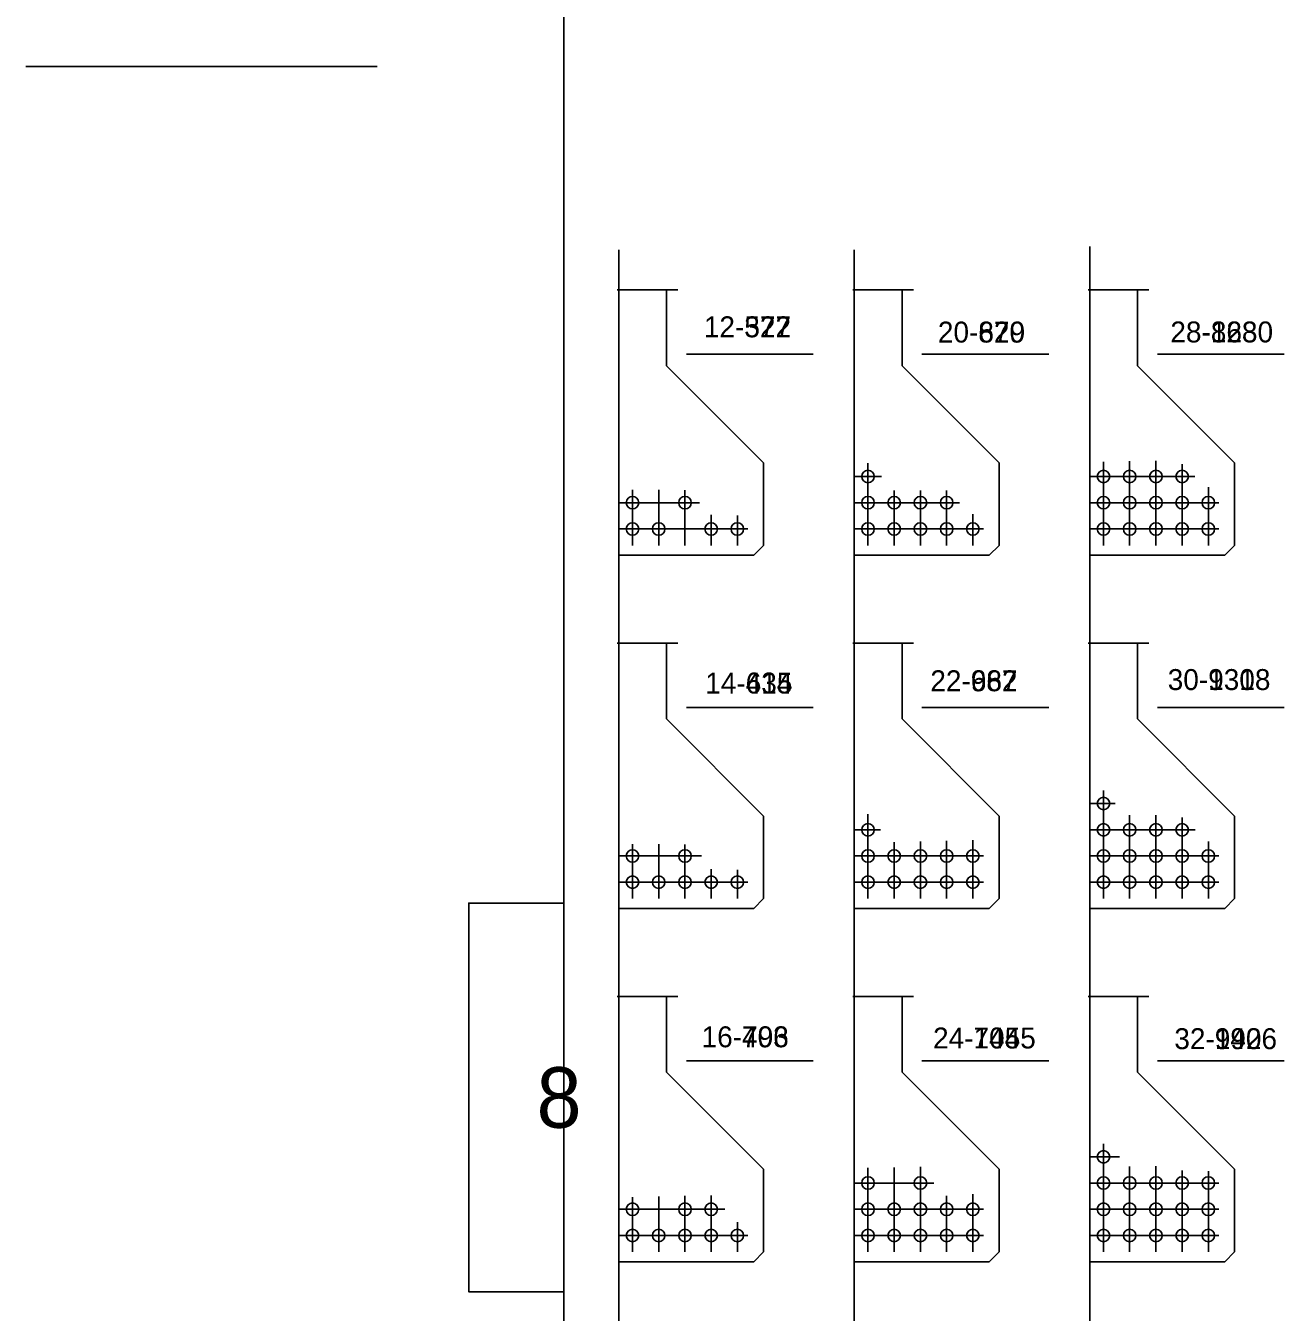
# Model space of a CAD drawing. Extents: x 1005.3 to 1101.9, y 1996.5 to 2073.3.
# Drawn here: x 1005.28 to 1025.32, y 2020.32 to 2040.81 of the extents above; entities that cross this region are included whole.
import ezdxf

# ---------------------------------------------------------------- set-up
doc = ezdxf.new("R2010")
doc.units = 0
for name, color, linetype in [('Level 1', 7, 'Continuous'), ('Level 37', 7, 'Continuous'), ('Level 8', 7, 'Continuous'), ('Level 9', 7, 'Continuous')]:
    doc.layers.add(name, color=color, linetype=linetype)

msp = doc.modelspace()

# ---------------------------------------------------------------- linework, layer by layer
at = {"layer": 'Level 1'}
msp.add_line((1013.852, 2012.158), (1013.852, 2068.156), dxfattribs=at)
msp.add_lwpolyline([(1013.851, 2026.837), (1012.338, 2026.837), (1012.338, 2020.647), (1013.851, 2020.647)], close=True, dxfattribs=at)
at = {"layer": 'Level 37'}
msp.add_line((1010.879, 2040.157), (1005.282, 2040.157), dxfattribs=at)
at = {"layer": 'Level 8'}
for p, q in [((1022.226, 2014.966), (1022.226, 2037.289)), ((1014.726, 2015.012), (1014.726, 2037.24)), ((1018.476, 2015.012), (1018.476, 2037.24)), ((1014.703, 2036.601), (1015.668, 2036.601)), ((1015.488, 2035.393), (1015.488, 2036.594)), ((1018.453, 2036.601), (1019.418, 2036.601)), ((1019.238, 2035.393), (1019.238, 2036.594)), ((1022.203, 2036.601), (1023.168, 2036.601)), ((1022.988, 2035.393), (1022.988, 2036.594)), ((1015.804, 2035.577), (1017.824, 2035.577)), ((1019.554, 2035.577), (1021.574, 2035.577)), ((1023.304, 2035.577), (1025.324, 2035.577)), ((1017.032, 2033.848), (1015.488, 2035.393)), ((1020.782, 2033.848), (1019.238, 2035.393)), ((1024.532, 2033.848), (1022.988, 2035.393)), ((1017.032, 2032.533), (1017.032, 2033.848)), ((1018.695, 2032.533), (1018.695, 2033.842)), ((1020.782, 2032.533), (1020.782, 2033.848)), ((1022.445, 2032.533), (1022.445, 2033.865)), ((1022.862, 2032.533), (1022.862, 2033.871)), ((1023.28, 2032.533), (1023.28, 2033.878)), ((1023.697, 2032.533), (1023.697, 2033.827)), ((1024.532, 2032.533), (1024.532, 2033.848)), ((1018.476, 2033.629), (1018.911, 2033.629)), ((1022.226, 2033.629), (1023.902, 2033.629)), ((1014.945, 2032.533), (1014.945, 2033.417)), ((1015.362, 2032.533), (1015.362, 2033.415)), ((1015.78, 2032.533), (1015.78, 2033.413)), ((1019.112, 2032.533), (1019.112, 2033.405)), ((1019.53, 2032.533), (1019.53, 2033.405)), ((1019.947, 2032.533), (1019.947, 2033.405)), ((1024.115, 2032.533), (1024.115, 2033.459)), ((1014.726, 2033.212), (1016.01, 2033.212)), ((1018.476, 2033.212), (1020.152, 2033.212)), ((1018.476, 2033.212), (1020.144, 2033.212)), ((1022.226, 2033.212), (1024.283, 2033.212)), ((1016.197, 2032.533), (1016.197, 2033.017)), ((1016.615, 2032.533), (1016.615, 2033.009)), ((1020.365, 2032.533), (1020.365, 2033.028)), ((1014.726, 2032.794), (1016.783, 2032.794)), ((1018.476, 2032.794), (1020.533, 2032.794)), ((1022.226, 2032.794), (1024.283, 2032.794)), ((1016.876, 2032.376), (1017.032, 2032.533)), ((1020.626, 2032.376), (1020.782, 2032.533)), ((1024.376, 2032.376), (1024.532, 2032.533)), ((1016.876, 2032.376), (1014.726, 2032.376)), ((1020.626, 2032.376), (1018.476, 2032.376)), ((1024.376, 2032.376), (1022.226, 2032.376)), ((1014.703, 2030.976), (1015.668, 2030.976)), ((1015.488, 2029.768), (1015.488, 2030.969)), ((1018.453, 2030.976), (1019.418, 2030.976)), ((1019.238, 2029.768), (1019.238, 2030.969)), ((1022.203, 2030.976), (1023.168, 2030.976)), ((1022.988, 2029.768), (1022.988, 2030.969)), ((1015.804, 2029.952), (1017.824, 2029.952)), ((1019.554, 2029.952), (1021.574, 2029.952)), ((1023.304, 2029.952), (1025.324, 2029.952)), ((1017.032, 2028.223), (1015.488, 2029.768)), ((1020.782, 2028.223), (1019.238, 2029.768)), ((1024.532, 2028.223), (1022.988, 2029.768)), ((1022.445, 2026.908), (1022.445, 2028.632)), ((1018.695, 2026.908), (1018.695, 2028.255)), ((1022.226, 2028.422), (1022.633, 2028.422)), ((1022.862, 2026.908), (1022.862, 2028.235)), ((1023.28, 2026.908), (1023.28, 2028.239)), ((1017.032, 2026.908), (1017.032, 2028.223)), ((1020.782, 2026.908), (1020.782, 2028.223)), ((1023.697, 2026.908), (1023.697, 2028.202)), ((1024.532, 2026.908), (1024.532, 2028.223)), ((1018.476, 2028.004), (1018.894, 2028.004)), ((1019.53, 2026.908), (1019.53, 2027.818)), ((1019.947, 2026.908), (1019.947, 2027.828)), ((1020.365, 2026.908), (1020.365, 2027.838)), ((1022.226, 2028.004), (1023.903, 2028.004)), ((1024.115, 2026.908), (1024.115, 2027.818)), ((1014.945, 2026.908), (1014.945, 2027.776)), ((1015.362, 2026.908), (1015.362, 2027.774)), ((1015.78, 2026.908), (1015.78, 2027.771)), ((1019.112, 2026.908), (1019.112, 2027.807)), ((1014.726, 2027.587), (1016.041, 2027.587)), ((1018.476, 2027.587), (1020.533, 2027.587)), ((1022.226, 2027.587), (1024.283, 2027.587)), ((1022.226, 2027.587), (1024.283, 2027.587)), ((1016.197, 2026.908), (1016.197, 2027.376)), ((1016.615, 2026.908), (1016.615, 2027.368)), ((1014.726, 2027.169), (1016.783, 2027.169)), ((1018.476, 2027.169), (1020.533, 2027.169)), ((1022.226, 2027.169), (1024.283, 2027.169)), ((1016.876, 2026.751), (1017.032, 2026.908)), ((1020.626, 2026.751), (1020.782, 2026.908)), ((1024.376, 2026.751), (1024.532, 2026.908)), ((1016.876, 2026.751), (1014.726, 2026.751)), ((1020.626, 2026.751), (1018.476, 2026.751)), ((1024.376, 2026.751), (1022.226, 2026.751)), ((1014.703, 2025.351), (1015.668, 2025.351)), ((1015.488, 2024.143), (1015.488, 2025.344)), ((1018.453, 2025.351), (1019.418, 2025.351)), ((1019.238, 2024.143), (1019.238, 2025.344)), ((1022.203, 2025.351), (1023.168, 2025.351)), ((1022.988, 2024.143), (1022.988, 2025.344)), ((1017.032, 2022.598), (1015.488, 2024.143)), ((1015.804, 2024.327), (1017.824, 2024.327)), ((1020.782, 2022.598), (1019.238, 2024.143)), ((1019.554, 2024.327), (1021.574, 2024.327)), ((1024.532, 2022.598), (1022.988, 2024.143)), ((1023.304, 2024.327), (1025.324, 2024.327)), ((1022.445, 2021.283), (1022.445, 2023.002)), ((1022.226, 2022.797), (1022.698, 2022.797)), ((1017.032, 2021.283), (1017.032, 2022.598)), ((1018.695, 2021.283), (1018.695, 2022.619)), ((1019.112, 2021.283), (1019.112, 2022.628)), ((1019.53, 2021.283), (1019.53, 2022.637)), ((1020.782, 2021.283), (1020.782, 2022.598)), ((1022.862, 2021.283), (1022.862, 2022.643)), ((1023.28, 2021.283), (1023.28, 2022.647)), ((1023.697, 2021.283), (1023.697, 2022.577)), ((1024.115, 2021.283), (1024.115, 2022.569)), ((1024.532, 2021.283), (1024.532, 2022.598)), ((1018.476, 2022.379), (1019.742, 2022.379)), ((1022.226, 2022.379), (1024.283, 2022.379)), ((1014.945, 2021.283), (1014.945, 2022.155)), ((1015.362, 2021.283), (1015.362, 2022.165)), ((1015.78, 2021.283), (1015.78, 2022.174)), ((1016.197, 2021.283), (1016.197, 2022.183)), ((1019.947, 2021.283), (1019.947, 2022.173)), ((1020.365, 2021.283), (1020.365, 2022.2)), ((1014.726, 2021.962), (1016.416, 2021.962)), ((1018.476, 2021.962), (1020.533, 2021.962)), ((1022.226, 2021.962), (1024.283, 2021.962)), ((1016.615, 2021.283), (1016.615, 2021.755)), ((1014.726, 2021.544), (1016.783, 2021.544)), ((1018.476, 2021.544), (1020.533, 2021.544)), ((1022.226, 2021.544), (1024.283, 2021.544)), ((1016.876, 2021.126), (1017.032, 2021.283)), ((1020.626, 2021.126), (1020.782, 2021.283)), ((1024.376, 2021.126), (1024.532, 2021.283)), ((1016.876, 2021.126), (1014.726, 2021.126)), ((1020.626, 2021.126), (1018.476, 2021.126)), ((1024.376, 2021.126), (1022.226, 2021.126))]:
    msp.add_line(p, q, dxfattribs=at)
for centre in [(1018.695, 2033.629), (1022.445, 2033.629), (1022.862, 2033.629), (1023.28, 2033.629), (1023.697, 2033.629), (1014.945, 2033.212), (1015.78, 2033.212), (1018.695, 2033.212), (1019.112, 2033.212), (1019.53, 2033.212), (1019.947, 2033.212), (1022.445, 2033.212), (1022.862, 2033.212), (1023.28, 2033.212), (1023.697, 2033.212), (1024.115, 2033.212), (1014.945, 2032.794), (1015.362, 2032.794), (1016.197, 2032.794), (1016.615, 2032.794), (1018.695, 2032.794), (1019.112, 2032.794), (1019.53, 2032.794), (1019.947, 2032.794), (1020.365, 2032.794), (1022.445, 2032.794), (1022.862, 2032.794), (1023.28, 2032.794), (1023.697, 2032.794), (1024.115, 2032.794), (1022.445, 2028.422), (1018.695, 2028.004), (1022.445, 2028.004), (1022.862, 2028.004), (1023.28, 2028.004), (1023.697, 2028.004), (1014.945, 2027.587), (1015.78, 2027.587), (1018.695, 2027.587), (1019.112, 2027.587), (1019.53, 2027.587), (1019.947, 2027.587), (1020.365, 2027.587), (1022.445, 2027.587), (1022.862, 2027.587), (1023.28, 2027.587), (1023.697, 2027.587), (1024.115, 2027.587), (1014.945, 2027.169), (1015.362, 2027.169), (1015.78, 2027.169), (1016.197, 2027.169), (1016.615, 2027.169), (1018.695, 2027.169), (1019.112, 2027.169), (1019.53, 2027.169), (1019.947, 2027.169), (1020.365, 2027.169), (1022.445, 2027.169), (1022.862, 2027.169), (1023.28, 2027.169), (1023.697, 2027.169), (1024.115, 2027.169), (1022.445, 2022.797), (1018.695, 2022.379), (1019.53, 2022.379), (1022.445, 2022.379), (1022.862, 2022.379), (1023.28, 2022.379), (1023.697, 2022.379), (1024.115, 2022.379), (1014.945, 2021.962), (1015.78, 2021.962), (1016.197, 2021.962), (1018.695, 2021.962), (1019.112, 2021.962), (1019.53, 2021.962), (1019.947, 2021.962), (1020.365, 2021.962), (1022.445, 2021.962), (1022.862, 2021.962), (1023.28, 2021.962), (1023.697, 2021.962), (1024.115, 2021.962), (1014.945, 2021.544), (1015.362, 2021.544), (1015.78, 2021.544), (1016.197, 2021.544), (1016.615, 2021.544), (1018.695, 2021.544), (1019.112, 2021.544), (1019.53, 2021.544), (1019.947, 2021.544), (1020.365, 2021.544), (1022.445, 2021.544), (1022.862, 2021.544), (1023.28, 2021.544), (1023.697, 2021.544), (1024.115, 2021.544)]:
    msp.add_circle(centre, 0.0996, dxfattribs=at)
at = {"layer": 'Level 9'}
for p, q in [((1022.226, 2014.966), (1022.226, 2037.289)), ((1014.726, 2015.012), (1014.726, 2037.24)), ((1018.476, 2015.012), (1018.476, 2037.24)), ((1014.703, 2036.601), (1015.668, 2036.601)), ((1015.488, 2035.393), (1015.488, 2036.594)), ((1018.453, 2036.601), (1019.418, 2036.601)), ((1019.238, 2035.393), (1019.238, 2036.594)), ((1022.203, 2036.601), (1023.168, 2036.601)), ((1022.988, 2035.393), (1022.988, 2036.594)), ((1015.804, 2035.577), (1017.824, 2035.577)), ((1019.554, 2035.577), (1021.574, 2035.577)), ((1023.304, 2035.577), (1025.324, 2035.577)), ((1017.032, 2033.848), (1015.488, 2035.393)), ((1020.782, 2033.848), (1019.238, 2035.393)), ((1024.532, 2033.848), (1022.988, 2035.393)), ((1017.032, 2032.533), (1017.032, 2033.848)), ((1018.695, 2032.533), (1018.695, 2033.842)), ((1020.782, 2032.533), (1020.782, 2033.848)), ((1022.445, 2032.533), (1022.445, 2033.865)), ((1022.862, 2032.533), (1022.862, 2033.871)), ((1023.28, 2032.533), (1023.28, 2033.878)), ((1023.697, 2032.533), (1023.697, 2033.827)), ((1024.532, 2032.533), (1024.532, 2033.848)), ((1018.476, 2033.629), (1018.911, 2033.629)), ((1022.226, 2033.629), (1023.902, 2033.629)), ((1014.945, 2032.533), (1014.945, 2033.417)), ((1015.362, 2032.533), (1015.362, 2033.415)), ((1015.78, 2032.533), (1015.78, 2033.413)), ((1019.112, 2032.533), (1019.112, 2033.405)), ((1019.53, 2032.533), (1019.53, 2033.405)), ((1019.947, 2032.533), (1019.947, 2033.405)), ((1024.115, 2032.533), (1024.115, 2033.459)), ((1014.726, 2033.212), (1016.01, 2033.212)), ((1018.476, 2033.212), (1020.152, 2033.212)), ((1018.476, 2033.212), (1020.144, 2033.212)), ((1022.226, 2033.212), (1024.283, 2033.212)), ((1016.197, 2032.533), (1016.197, 2033.017)), ((1016.615, 2032.533), (1016.615, 2033.009)), ((1020.365, 2032.533), (1020.365, 2033.028)), ((1014.726, 2032.794), (1016.783, 2032.794)), ((1018.476, 2032.794), (1020.533, 2032.794)), ((1022.226, 2032.794), (1024.283, 2032.794)), ((1016.876, 2032.376), (1017.032, 2032.533)), ((1020.626, 2032.376), (1020.782, 2032.533)), ((1024.376, 2032.376), (1024.532, 2032.533)), ((1016.876, 2032.376), (1014.726, 2032.376)), ((1020.626, 2032.376), (1018.476, 2032.376)), ((1024.376, 2032.376), (1022.226, 2032.376)), ((1014.703, 2030.976), (1015.668, 2030.976)), ((1015.488, 2029.768), (1015.488, 2030.969)), ((1018.453, 2030.976), (1019.418, 2030.976)), ((1019.238, 2029.768), (1019.238, 2030.969)), ((1022.203, 2030.976), (1023.168, 2030.976)), ((1022.988, 2029.768), (1022.988, 2030.969)), ((1015.804, 2029.952), (1017.824, 2029.952)), ((1019.554, 2029.952), (1021.574, 2029.952)), ((1023.304, 2029.952), (1025.324, 2029.952)), ((1017.032, 2028.223), (1015.488, 2029.768)), ((1020.782, 2028.223), (1019.238, 2029.768)), ((1024.532, 2028.223), (1022.988, 2029.768)), ((1022.445, 2026.908), (1022.445, 2028.632)), ((1018.695, 2026.908), (1018.695, 2028.255)), ((1022.226, 2028.422), (1022.633, 2028.422)), ((1022.862, 2026.908), (1022.862, 2028.235)), ((1023.28, 2026.908), (1023.28, 2028.239)), ((1017.032, 2026.908), (1017.032, 2028.223)), ((1020.782, 2026.908), (1020.782, 2028.223)), ((1023.697, 2026.908), (1023.697, 2028.202)), ((1024.532, 2026.908), (1024.532, 2028.223)), ((1018.476, 2028.004), (1018.894, 2028.004)), ((1019.53, 2026.908), (1019.53, 2027.818)), ((1019.947, 2026.908), (1019.947, 2027.828)), ((1020.365, 2026.908), (1020.365, 2027.838)), ((1022.226, 2028.004), (1023.903, 2028.004)), ((1024.115, 2026.908), (1024.115, 2027.818)), ((1014.945, 2026.908), (1014.945, 2027.776)), ((1015.362, 2026.908), (1015.362, 2027.774)), ((1015.78, 2026.908), (1015.78, 2027.771)), ((1019.112, 2026.908), (1019.112, 2027.807)), ((1014.726, 2027.587), (1016.041, 2027.587)), ((1018.476, 2027.587), (1020.533, 2027.587)), ((1022.226, 2027.587), (1024.283, 2027.587)), ((1022.226, 2027.587), (1024.283, 2027.587)), ((1016.197, 2026.908), (1016.197, 2027.376)), ((1016.615, 2026.908), (1016.615, 2027.368)), ((1014.726, 2027.169), (1016.783, 2027.169)), ((1018.476, 2027.169), (1020.533, 2027.169)), ((1022.226, 2027.169), (1024.283, 2027.169)), ((1016.876, 2026.751), (1017.032, 2026.908)), ((1020.626, 2026.751), (1020.782, 2026.908)), ((1024.376, 2026.751), (1024.532, 2026.908)), ((1016.876, 2026.751), (1014.726, 2026.751)), ((1020.626, 2026.751), (1018.476, 2026.751)), ((1024.376, 2026.751), (1022.226, 2026.751)), ((1014.703, 2025.351), (1015.668, 2025.351)), ((1015.488, 2024.143), (1015.488, 2025.344)), ((1018.453, 2025.351), (1019.418, 2025.351)), ((1019.238, 2024.143), (1019.238, 2025.344)), ((1022.203, 2025.351), (1023.168, 2025.351)), ((1022.988, 2024.143), (1022.988, 2025.344)), ((1017.032, 2022.598), (1015.488, 2024.143)), ((1015.804, 2024.327), (1017.824, 2024.327)), ((1020.782, 2022.598), (1019.238, 2024.143)), ((1019.554, 2024.327), (1021.574, 2024.327)), ((1024.532, 2022.598), (1022.988, 2024.143)), ((1023.304, 2024.327), (1025.324, 2024.327)), ((1022.445, 2021.283), (1022.445, 2023.002)), ((1022.226, 2022.797), (1022.698, 2022.797)), ((1017.032, 2021.283), (1017.032, 2022.598)), ((1018.695, 2021.283), (1018.695, 2022.619)), ((1019.112, 2021.283), (1019.112, 2022.628)), ((1019.53, 2021.283), (1019.53, 2022.637)), ((1020.782, 2021.283), (1020.782, 2022.598)), ((1022.862, 2021.283), (1022.862, 2022.643)), ((1023.28, 2021.283), (1023.28, 2022.647)), ((1023.697, 2021.283), (1023.697, 2022.577)), ((1024.115, 2021.283), (1024.115, 2022.569)), ((1024.532, 2021.283), (1024.532, 2022.598)), ((1018.476, 2022.379), (1019.742, 2022.379)), ((1022.226, 2022.379), (1024.283, 2022.379)), ((1014.945, 2021.283), (1014.945, 2022.155)), ((1015.362, 2021.283), (1015.362, 2022.165)), ((1015.78, 2021.283), (1015.78, 2022.174)), ((1016.197, 2021.283), (1016.197, 2022.183)), ((1019.947, 2021.283), (1019.947, 2022.173)), ((1020.365, 2021.283), (1020.365, 2022.2)), ((1014.726, 2021.962), (1016.416, 2021.962)), ((1018.476, 2021.962), (1020.533, 2021.962)), ((1022.226, 2021.962), (1024.283, 2021.962)), ((1016.615, 2021.283), (1016.615, 2021.755)), ((1014.726, 2021.544), (1016.783, 2021.544)), ((1018.476, 2021.544), (1020.533, 2021.544)), ((1022.226, 2021.544), (1024.283, 2021.544)), ((1016.876, 2021.126), (1017.032, 2021.283)), ((1020.626, 2021.126), (1020.782, 2021.283)), ((1024.376, 2021.126), (1024.532, 2021.283)), ((1016.876, 2021.126), (1014.726, 2021.126)), ((1020.626, 2021.126), (1018.476, 2021.126)), ((1024.376, 2021.126), (1022.226, 2021.126))]:
    msp.add_line(p, q, dxfattribs=at)
for centre in [(1018.695, 2033.629), (1022.445, 2033.629), (1022.862, 2033.629), (1023.28, 2033.629), (1023.697, 2033.629), (1014.945, 2033.212), (1015.78, 2033.212), (1018.695, 2033.212), (1019.112, 2033.212), (1019.53, 2033.212), (1019.947, 2033.212), (1022.445, 2033.212), (1022.862, 2033.212), (1023.28, 2033.212), (1023.697, 2033.212), (1024.115, 2033.212), (1014.945, 2032.794), (1015.362, 2032.794), (1016.197, 2032.794), (1016.615, 2032.794), (1018.695, 2032.794), (1019.112, 2032.794), (1019.53, 2032.794), (1019.947, 2032.794), (1020.365, 2032.794), (1022.445, 2032.794), (1022.862, 2032.794), (1023.28, 2032.794), (1023.697, 2032.794), (1024.115, 2032.794), (1022.445, 2028.422), (1018.695, 2028.004), (1022.445, 2028.004), (1022.862, 2028.004), (1023.28, 2028.004), (1023.697, 2028.004), (1014.945, 2027.587), (1015.78, 2027.587), (1018.695, 2027.587), (1019.112, 2027.587), (1019.53, 2027.587), (1019.947, 2027.587), (1020.365, 2027.587), (1022.445, 2027.587), (1022.862, 2027.587), (1023.28, 2027.587), (1023.697, 2027.587), (1024.115, 2027.587), (1014.945, 2027.169), (1015.362, 2027.169), (1015.78, 2027.169), (1016.197, 2027.169), (1016.615, 2027.169), (1018.695, 2027.169), (1019.112, 2027.169), (1019.53, 2027.169), (1019.947, 2027.169), (1020.365, 2027.169), (1022.445, 2027.169), (1022.862, 2027.169), (1023.28, 2027.169), (1023.697, 2027.169), (1024.115, 2027.169), (1022.445, 2022.797), (1018.695, 2022.379), (1019.53, 2022.379), (1022.445, 2022.379), (1022.862, 2022.379), (1023.28, 2022.379), (1023.697, 2022.379), (1024.115, 2022.379), (1014.945, 2021.962), (1015.78, 2021.962), (1016.197, 2021.962), (1018.695, 2021.962), (1019.112, 2021.962), (1019.53, 2021.962), (1019.947, 2021.962), (1020.365, 2021.962), (1022.445, 2021.962), (1022.862, 2021.962), (1023.28, 2021.962), (1023.697, 2021.962), (1024.115, 2021.962), (1014.945, 2021.544), (1015.362, 2021.544), (1015.78, 2021.544), (1016.197, 2021.544), (1016.615, 2021.544), (1018.695, 2021.544), (1019.112, 2021.544), (1019.53, 2021.544), (1019.947, 2021.544), (1020.365, 2021.544), (1022.445, 2021.544), (1022.862, 2021.544), (1023.28, 2021.544), (1023.697, 2021.544), (1024.115, 2021.544)]:
    msp.add_circle(centre, 0.0996, dxfattribs=at)

# ---------------------------------------------------------------- texts
at = {"layer": 'Level 1'}
msp.add_text('8', height=0.963, dxfattribs=at).set_placement((1013.417, 2023.26))
at = {"layer": 'Level 8'}
for s, p in [('12-372 ', (1016.081, 2035.846)), ('20-620 ', (1019.808, 2035.762)), ('28-868 ', (1023.51, 2035.764)), ('14-434 ', (1016.103, 2030.174)), ('22-682 ', (1019.688, 2030.21)), ('30-930 ', (1023.468, 2030.229)), ('16-496 ', (1016.045, 2024.541)), ('24-744 ', (1019.731, 2024.522)), ('32-992 ', (1023.573, 2024.511))]:
    msp.add_text(s, height=0.3333, dxfattribs=at).set_placement(p)
at = {"layer": 'Level 9'}
for s, p in [('12-527', (1016.081, 2035.846)), ('20-879', (1019.808, 2035.762)), ('28-1230', (1023.51, 2035.764)), ('14-615', (1016.103, 2030.174)), ('22-967', (1019.688, 2030.21)), ('30-1318', (1023.468, 2030.229)), ('16-703', (1016.045, 2024.541)), ('24-1055', (1019.731, 2024.522)), ('32-1406', (1023.573, 2024.511))]:
    msp.add_text(s, height=0.3333, dxfattribs=at).set_placement(p)

doc.saveas('drawing.dxf')
